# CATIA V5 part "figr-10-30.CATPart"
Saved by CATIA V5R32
Part number: Part1
Bounding box of the stored display mesh (mm): x -72 to 28.909, y -84.823 to 54.826, z -29.324 to 42.024
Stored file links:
  D:\PROJECTS\Project 2022\CATIA V5 6R 2022\Resources\Part Files\c10_catia_v5_6r2022_prt\c10_catia_v5_6r2022_prt\figr-10-30.CATPart
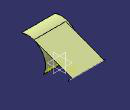
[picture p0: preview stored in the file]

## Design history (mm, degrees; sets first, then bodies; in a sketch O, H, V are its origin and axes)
Body1 (main body)
  Sketch1 on yz-plane, origin (0, 0, 0), H (0, 1, 0), V (0, 0, 1)
    arc A1 centre (-67.861, -7.2287) radius 49.2558 from (-84.8225, 39.0145) to (-23.8391, -29.3242) cw
  Extrude1: Element1 Sketch1, Lim1 20, Lim2 72
  Sketch2 on xy-plane, origin (0, 0, 0), H (1, 0, 0), V (0, 1, 0)
    line L1 (-67.3145, 54.8256) -> (28.9089, 54.8256)
    horizontal: L1 H
  Sweep1: type Segment, GuideCrv Sketch2, GuideSurf Extrude1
